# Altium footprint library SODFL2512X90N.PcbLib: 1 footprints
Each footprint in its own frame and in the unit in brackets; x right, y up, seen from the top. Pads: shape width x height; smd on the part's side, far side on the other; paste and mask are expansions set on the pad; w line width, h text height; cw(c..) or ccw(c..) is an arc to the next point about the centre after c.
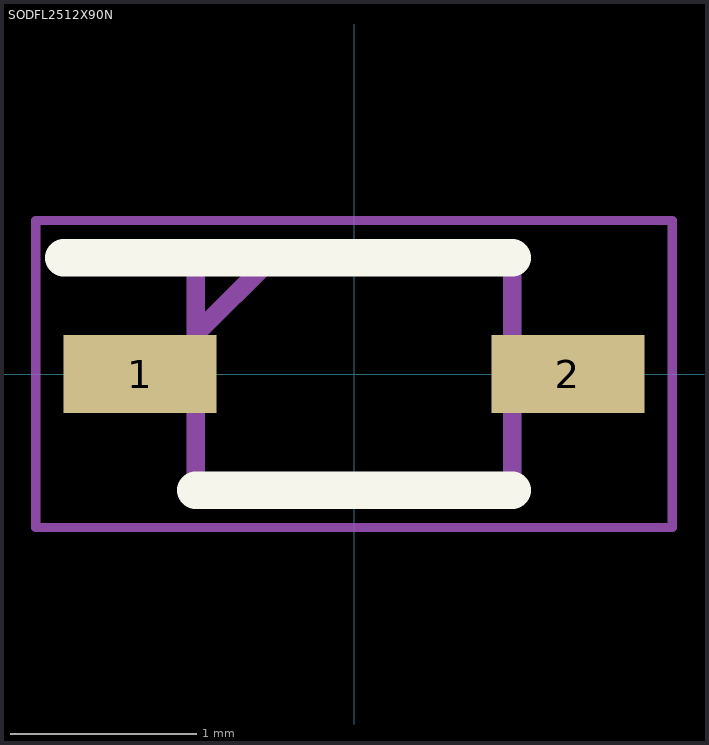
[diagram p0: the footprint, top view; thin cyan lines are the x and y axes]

## SODFL2512X90N [mm]
pads (2):
  rect 0.82x0.42 smd: 1(-1.15,0) 2(1.15,0)
Top Overlay:
  lines w0.2: -1.56,0.625 0.85,0.625 ; -0.85,-0.625 0.85,-0.625
Mechanical 15:
  lines w0.1: -0.85,0.215 -0.44,0.625 ; -0.85,-0.625 0.85,-0.625 0.85,0.625 -0.85,0.625 -0.85,-0.625
Mechanical 20:
  lines w0.05: -1.71,-0.825 1.71,-0.825 1.71,0.825 -1.71,0.825 -1.71,-0.825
